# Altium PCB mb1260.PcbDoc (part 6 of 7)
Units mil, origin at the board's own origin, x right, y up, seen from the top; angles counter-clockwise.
Board outline 3189.01 x 3818.89 mil, 6 copper layers (TOP, L2_GND, L3_VCC, L4_SIG, L5_GND, BOTTOM), stack 62.2 mil thick; 308 components, 287 nets, 1220 pads, 851 vias.
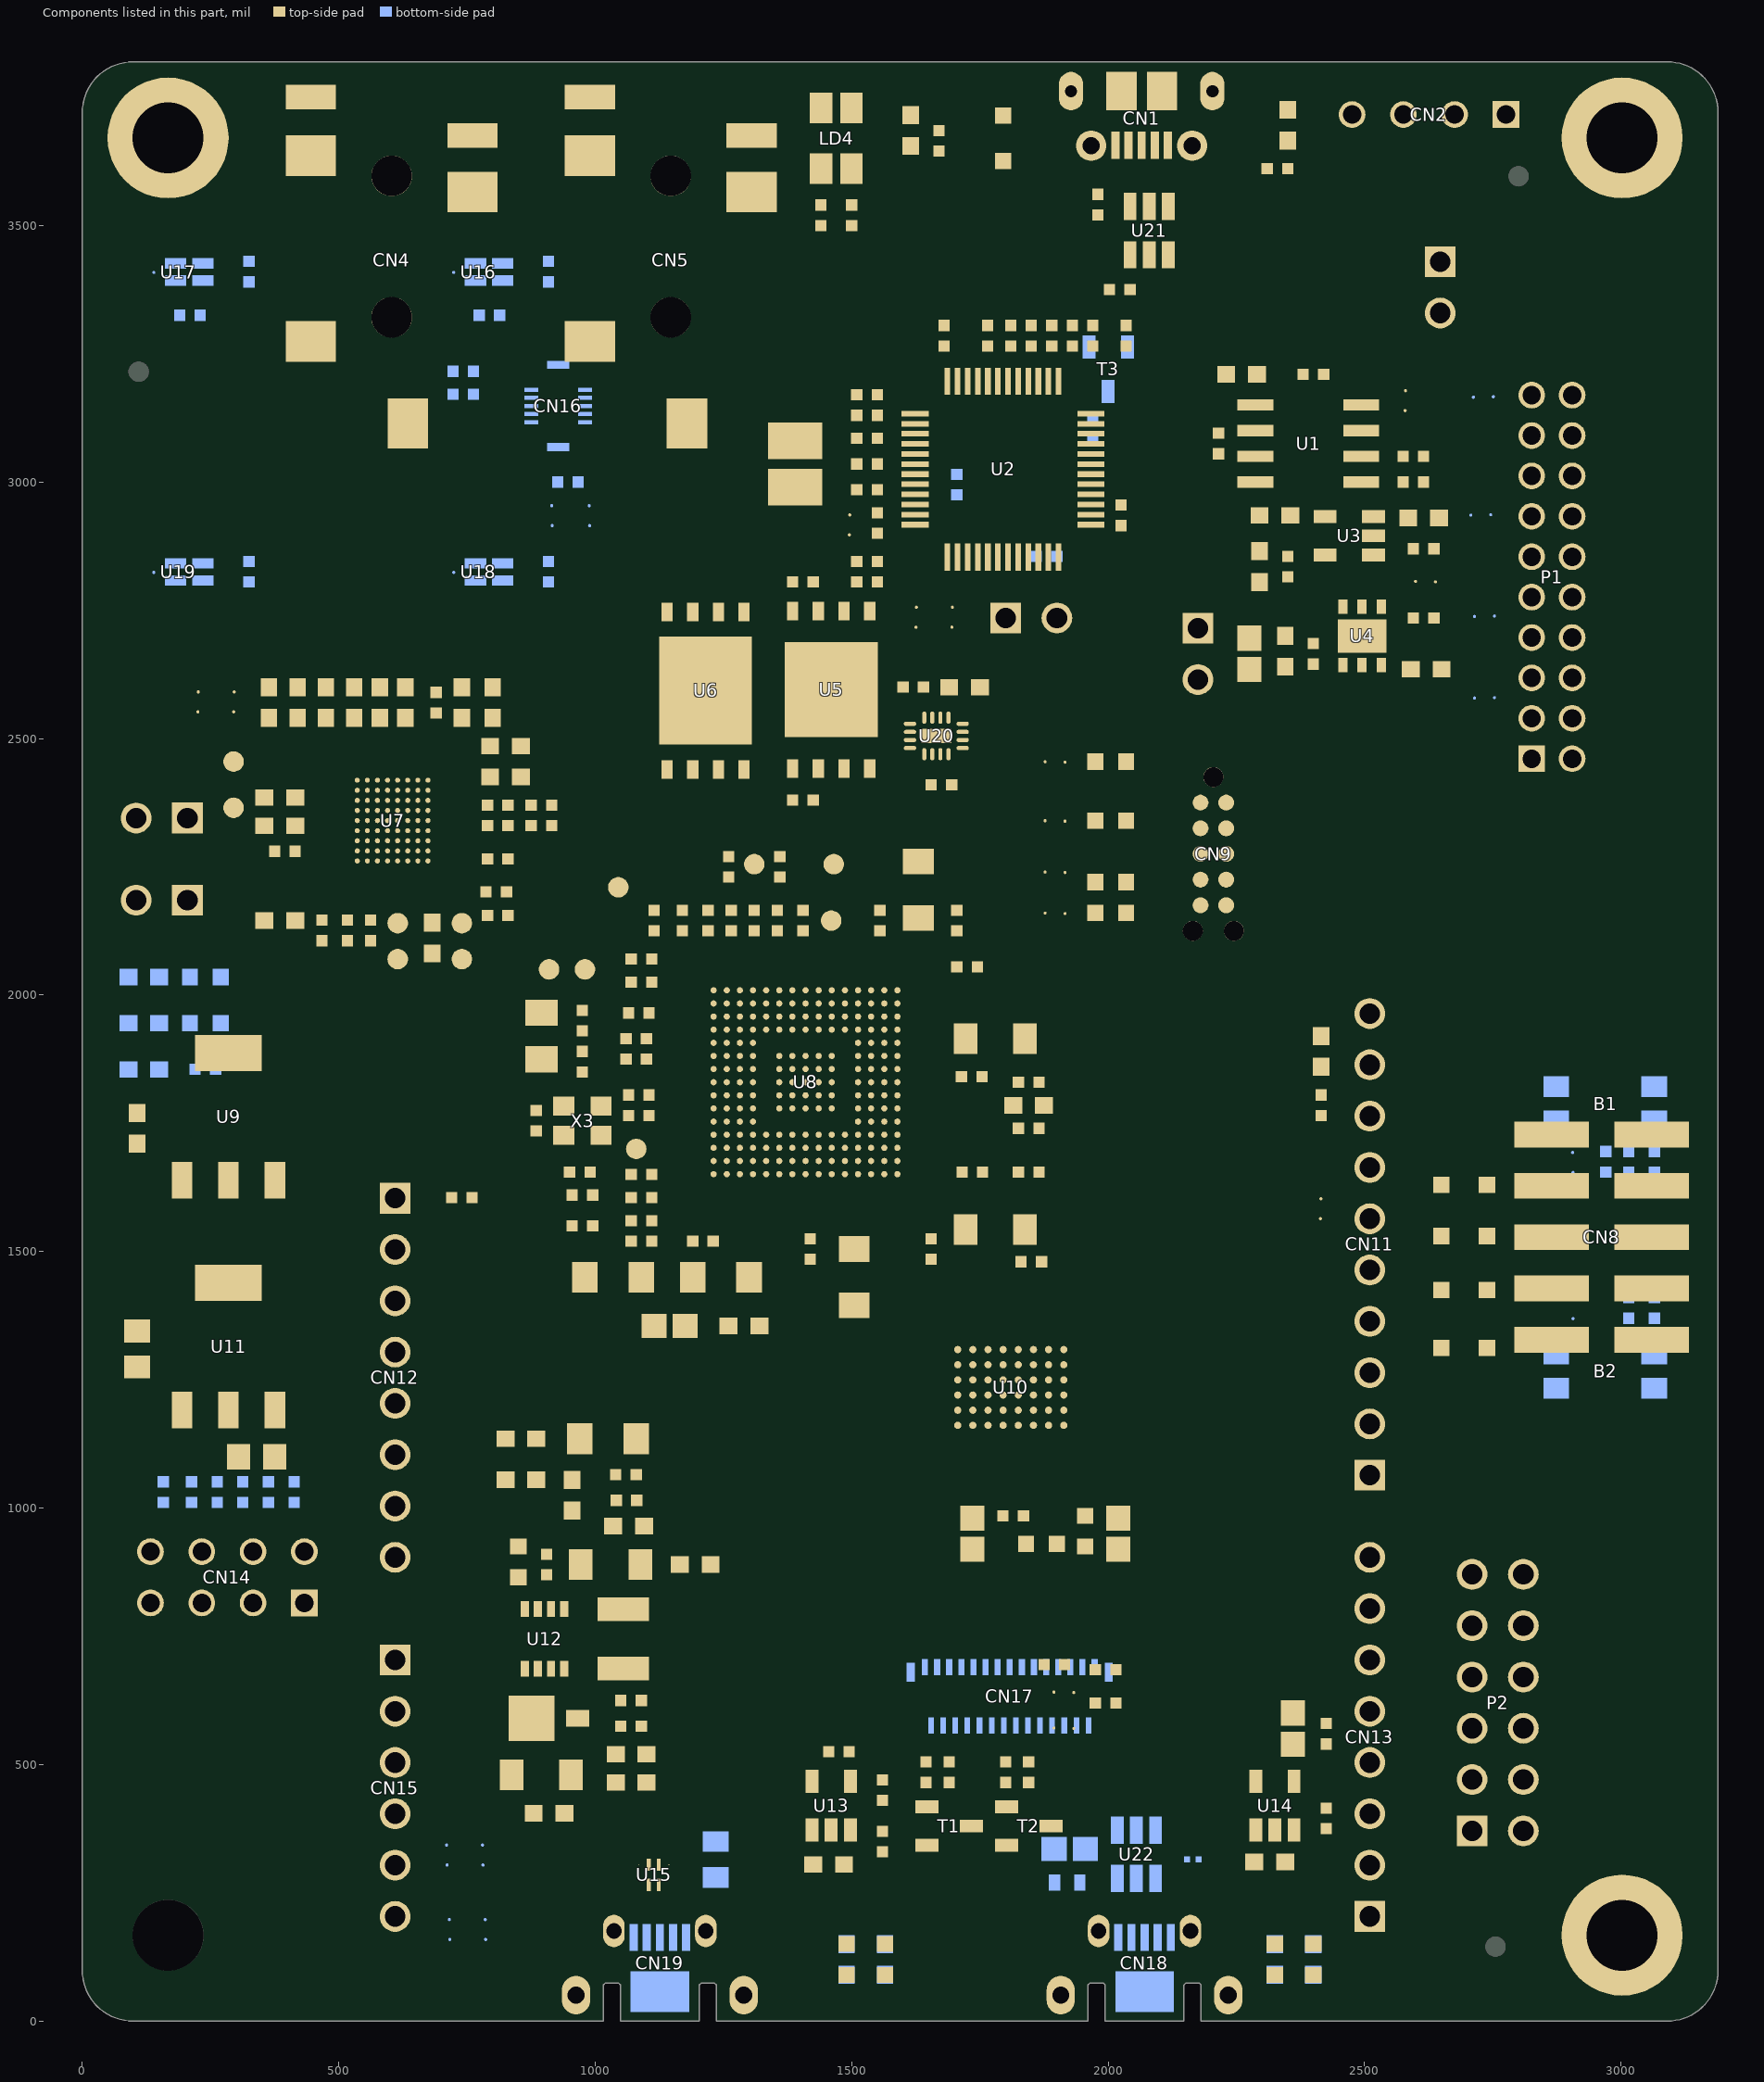
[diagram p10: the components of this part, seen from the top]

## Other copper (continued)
L2_GND (plane layer: these items are gaps in the copper):
  rectangle: -21.66,-14.67 557.59,549.61
  rectangle: 2273.23,973.39 2419.77,1532.61
  pour cut-out: -6000,-8000 -5990,-8000 -5990,-7990 -6000,-7990
  pour cut-out: -6000,-8000 -5990,-8000 -5990,-7990 -6000,-7990
  pour cut-out: -6000,-8000 -5990,-8000 -5990,-7990 -6000,-7990
  pour cut-out: -6000,-8000 -5990,-8000 -5990,-7990 -6000,-7990
  pour cut-out: -6000,-8000 -5990,-8000 -5990,-7990 -6000,-7990
  pour cut-out: -6000,-8000 -5990,-8000 -5990,-7990 -6000,-7990
  pour cut-out: -6000,-8000 -5990,-8000 -5990,-7990 -6000,-7990
  pour cut-out: -6000,-8000 -5990,-8000 -5990,-7990 -6000,-7990
  pour cut-out: -6000,-8000 -5990,-8000 -5990,-7990 -6000,-7990
  pour cut-out: -6000,-8000 -5990,-8000 -5990,-7990 -6000,-7990
  pour cut-out: -6000,-8000 -5990,-8000 -5990,-7990 -6000,-7990
  pour cut-out: -6000,-8000 -5990,-8000 -5990,-7990 -6000,-7990
  pour cut-out: -6000,-8000 -5990,-8000 -5990,-7990 -6000,-7990
  pour cut-out: -6000,-8000 -5990,-8000 -5990,-7990 -6000,-7990
  pour cut-out: -6000,-8000 -5990,-8000 -5990,-7990 -6000,-7990
  pour cut-out: -6000,-8000 -5990,-8000 -5990,-7990 -6000,-7990
  pour cut-out: -6000,-8000 -5990,-8000 -5990,-7990 -6000,-7990
  pour cut-out: -6000,-8000 -5990,-8000 -5990,-7990 -6000,-7990
  pour cut-out: -6000,-8000 -5990,-8000 -5990,-7990 -6000,-7990
  pour cut-out: -6000,-8000 -5990,-8000 -5990,-7990 -6000,-7990
  pour cut-out: -6000,-8000 -5990,-8000 -5990,-7990 -6000,-7990
  pour cut-out: -6000,-8000 -5990,-8000 -5990,-7990 -6000,-7990
  pour cut-out: -6000,-8000 -5990,-8000 -5990,-7990 -6000,-7990
  pour cut-out: -6000,-8000 -5990,-8000 -5990,-7990 -6000,-7990
  pour cut-out: -6000,-8000 -5990,-8000 -5990,-7990 -6000,-7990
  pour cut-out: -6000,-8000 -5990,-8000 -5990,-7990 -6000,-7990
  pour cut-out: -6000,-8000 -5990,-8000 -5990,-7990 -6000,-7990
  pour cut-out: -6000,-8000 -5990,-8000 -5990,-7990 -6000,-7990
  pour cut-out: -6000,-8000 -5990,-8000 -5990,-7990 -6000,-7990
  pour cut-out: -6000,-8000 -5990,-8000 -5990,-7990 -6000,-7990
  pour cut-out: -6000,-8000 -5990,-8000 -5990,-7990 -6000,-7990
  pour cut-out: -6000,-8000 -5990,-8000 -5990,-7990 -6000,-7990
  pour cut-out: -6000,-8000 -5990,-8000 -5990,-7990 -6000,-7990
  pour cut-out: -6000,-8000 -5990,-8000 -5990,-7990 -6000,-7990
  pour cut-out: -6000,-8000 -5990,-8000 -5990,-7990 -6000,-7990
  pour cut-out: -6000,-8000 -5990,-8000 -5990,-7990 -6000,-7990
  pour cut-out: -6000,-8000 -5990,-8000 -5990,-7990 -6000,-7990
  pour cut-out: -6000,-8000 -5990,-8000 -5990,-7990 -6000,-7990
  pour cut-out: -6000,-8000 -5990,-8000 -5990,-7990 -6000,-7990
  pour cut-out: -6000,-8000 -5990,-8000 -5990,-7990 -6000,-7990
  pour cut-out: -6000,-8000 -5990,-8000 -5990,-7990 -6000,-7990
  pour cut-out: -6000,-8000 -5990,-8000 -5990,-7990 -6000,-7990
  pour cut-out: -6000,-8000 -5990,-8000 -5990,-7990 -6000,-7990
  pour cut-out: -6000,-8000 -5990,-8000 -5990,-7990 -6000,-7990
  pour cut-out: -6000,-8000 -5990,-8000 -5990,-7990 -6000,-7990
  pour cut-out: -6000,-8000 -5990,-8000 -5990,-7990 -6000,-7990
  pour cut-out: -6000,-8000 -5990,-8000 -5990,-7990 -6000,-7990
  pour cut-out: -6000,-8000 -5990,-8000 -5990,-7990 -6000,-7990
  pour cut-out: -6000,-8000 -5990,-8000 -5990,-7990 -6000,-7990
  pour cut-out: -6000,-8000 -5990,-8000 -5990,-7990 -6000,-7990
  pour cut-out: -6000,-8000 -5990,-8000 -5990,-7990 -6000,-7990
  pour cut-out: -6000,-8000 -5990,-8000 -5990,-7990 -6000,-7990
  pour cut-out: -6000,-8000 -5990,-8000 -5990,-7990 -6000,-7990
  pour cut-out: -6000,-8000 -5990,-8000 -5990,-7990 -6000,-7990
  pour cut-out: -6000,-8000 -5990,-8000 -5990,-7990 -6000,-7990
  pour cut-out: -6000,-8000 -5990,-8000 -5990,-7990 -6000,-7990
  pour cut-out: -6000,-8000 -5990,-8000 -5990,-7990 -6000,-7990
  pour cut-out: -6000,-8000 -5990,-8000 -5990,-7990 -6000,-7990
  pour cut-out: -6000,-8000 -5990,-8000 -5990,-7990 -6000,-7990
  pour cut-out: -6000,-8000 -5990,-8000 -5990,-7990 -6000,-7990
  pour cut-out: -6000,-8000 -5990,-8000 -5990,-7990 -6000,-7990
  pour cut-out: -6000,-8000 -5990,-8000 -5990,-7990 -6000,-7990
  pour cut-out: -6000,-8000 -5990,-8000 -5990,-7990 -6000,-7990
  pour cut-out: -6000,-8000 -5990,-8000 -5990,-7990 -6000,-7990
  pour cut-out: -6000,-8000 -5990,-8000 -5990,-7990 -6000,-7990
  pour cut-out: -6000,-8000 -5990,-8000 -5990,-7990 -6000,-7990
  pour cut-out: -6000,-8000 -5990,-8000 -5990,-7990 -6000,-7990
  pour cut-out: -6000,-8000 -5990,-8000 -5990,-7990 -6000,-7990
  pour cut-out: -6000,-8000 -5990,-8000 -5990,-7990 -6000,-7990
  pour cut-out: -6000,-8000 -5990,-8000 -5990,-7990 -6000,-7990
  pour cut-out: 2240.77,2425 2239.55,2434.26 2235.98,2442.88 2230.29,2450.29 2222.88,2455.98 2214.26,2459.55 2205,2460.77 2195.74,2459.55 2187.12,2455.98 2179.71,2450.29 2174.02,2442.88 2170.45,2434.26 2169.23,2425 2170.45,2415.74 2174.02,2407.12 2179.71,2399.71 2187.12,2394.02 2195.74,2390.45 2205,2389.23 2214.26,2390.45 2222.88,2394.02 2230.29,2399.71 2235.98,2407.12 2239.55,2415.74 2240.77,2425
  pour cut-out: 2280.73,2125 2279.51,2134.26 2275.94,2142.88 2270.25,2150.29 2262.84,2155.97 2254.22,2159.55 2244.96,2160.77 2235.7,2159.55 2227.08,2155.97 2219.67,2150.29 2213.99,2142.88 2210.41,2134.26 2209.19,2125 2210.41,2115.74 2213.99,2107.12 2219.67,2099.71 2227.08,2094.03 2235.7,2090.45 2244.96,2089.23 2254.22,2090.45 2262.84,2094.03 2270.25,2099.71 2275.94,2107.12 2279.51,2115.74 2280.73,2125
  pour cut-out: 2200.81,2125 2199.59,2134.26 2196.01,2142.88 2190.33,2150.29 2182.92,2155.98 2174.3,2159.55 2165.04,2160.77 2155.78,2159.55 2147.16,2155.98 2139.75,2150.29 2134.06,2142.88 2130.49,2134.26 2129.27,2125 2130.49,2115.74 2134.06,2107.12 2139.75,2099.71 2147.16,2094.02 2155.78,2090.45 2165.04,2089.23 2174.3,2090.45 2182.92,2094.02 2190.33,2099.71 2196.01,2107.12 2199.59,2115.74 2200.81,2125
  pour cut-out: 1201.99,3596.61 1200.12,3610.8 1194.64,3624.02 1185.93,3635.38 1174.57,3644.09 1161.35,3649.57 1147.16,3651.44 1132.97,3649.57 1119.75,3644.09 1108.39,3635.38 1099.68,3624.02 1094.2,3610.8 1092.33,3596.61 1094.2,3582.42 1099.68,3569.2 1108.39,3557.84 1119.75,3549.13 1132.97,3543.65 1147.16,3541.78 1161.35,3543.65 1174.57,3549.13 1185.93,3557.84 1194.64,3569.2 1200.12,3582.42 1201.99,3596.61
  pour cut-out: 657.98,3596.61 656.11,3610.8 650.64,3624.03 641.92,3635.38 630.57,3644.1 617.34,3649.57 603.15,3651.44 588.96,3649.57 575.73,3644.1 564.38,3635.38 555.66,3624.03 550.19,3610.8 548.32,3596.61 550.19,3582.42 555.66,3569.19 564.38,3557.84 575.73,3549.12 588.96,3543.65 603.15,3541.78 617.34,3543.65 630.57,3549.12 641.92,3557.84 650.64,3569.19 656.11,3582.42 657.98,3596.61
  pour cut-out: 657.98,3321.02 656.11,3335.21 650.64,3348.43 641.92,3359.79 630.57,3368.5 617.34,3373.98 603.15,3375.85 588.96,3373.98 575.73,3368.5 564.38,3359.79 555.66,3348.43 550.19,3335.21 548.32,3321.02 550.19,3306.83 555.66,3293.6 564.38,3282.25 575.73,3273.53 588.96,3268.06 603.15,3266.19 617.34,3268.06 630.57,3273.53 641.92,3282.25 650.64,3293.6 656.11,3306.83 657.98,3321.02
  pour cut-out: -6000,-8000 -5990,-8000 -5990,-7990 -6000,-7990
  pour cut-out: -6000,-8000 -5990,-8000 -5990,-7990 -6000,-7990
  pour cut-out: -6000,-8000 -5990,-8000 -5990,-7990 -6000,-7990
  pour cut-out: -6000,-8000 -5990,-8000 -5990,-7990 -6000,-7990
  pour cut-out: -6000,-8000 -5990,-8000 -5990,-7990 -6000,-7990
  pour cut-out: -6000,-8000 -5990,-8000 -5990,-7990 -6000,-7990
  pour cut-out: -6000,-8000 -5990,-8000 -5990,-7990 -6000,-7990
  pour cut-out: -6000,-8000 -5990,-8000 -5990,-7990 -6000,-7990
  pour cut-out: -6000,-8000 -5990,-8000 -5990,-7990 -6000,-7990
  pour cut-out: -6000,-8000 -5990,-8000 -5990,-7990 -6000,-7990
  pour cut-out: -6000,-8000 -5990,-8000 -5990,-7990 -6000,-7990
  pour cut-out: -6000,-8000 -5990,-8000 -5990,-7990 -6000,-7990
  pour cut-out: -6000,-8000 -5990,-8000 -5990,-7990 -6000,-7990
  pour cut-out: -6000,-8000 -5990,-8000 -5990,-7990 -6000,-7990
  pour cut-out: 1201.99,3321.02 1200.12,3335.21 1194.64,3348.43 1185.93,3359.79 1174.57,3368.5 1161.35,3373.98 1147.16,3375.85 1132.97,3373.98 1119.75,3368.5 1108.39,3359.79 1099.68,3348.43 1094.2,3335.21 1092.33,3321.02 1094.2,3306.83 1099.68,3293.6 1108.39,3282.25 1119.75,3273.54 1132.97,3268.06 1147.16,3266.19 1161.35,3268.06 1174.57,3273.54 1185.93,3282.25 1194.64,3293.6 1200.12,3306.83 1201.99,3321.02
  pour cut-out: -6000,-8000 -5990,-8000 -5990,-7990 -6000,-7990
  pour cut-out: -6000,-8000 -5990,-8000 -5990,-7990 -6000,-7990
  pour cut-out: -6000,-8000 -5990,-8000 -5990,-7990 -6000,-7990
  pour cut-out: -6000,-8000 -5990,-8000 -5990,-7990 -6000,-7990
  pour cut-out: -6000,-8000 -5990,-8000 -5990,-7990 -6000,-7990
  pour cut-out: -6000,-8000 -5990,-8000 -5990,-7990 -6000,-7990
  pour cut-out: -6000,-8000 -5990,-8000 -5990,-7990 -6000,-7990
  pour cut-out: -6000,-8000 -5990,-8000 -5990,-7990 -6000,-7990
  pour cut-out: -6000,-8000 -5990,-8000 -5990,-7990 -6000,-7990
  pour cut-out: -6000,-8000 -5990,-8000 -5990,-7990 -6000,-7990
  pour cut-out: -6000,-8000 -5990,-8000 -5990,-7990 -6000,-7990
  pour cut-out: -6000,-8000 -5990,-8000 -5990,-7990 -6000,-7990
  pour cut-out: -6000,-8000 -5990,-8000 -5990,-7990 -6000,-7990
  pour cut-out: -6000,-8000 -5990,-8000 -5990,-7990 -6000,-7990
  pour cut-out: -6000,-8000 -5990,-8000 -5990,-7990 -6000,-7990
  pour cut-out: -6000,-8000 -5990,-8000 -5990,-7990 -6000,-7990
  pour cut-out: -6000,-8000 -5990,-8000 -5990,-7990 -6000,-7990
  pour cut-out: -6000,-8000 -5990,-8000 -5990,-7990 -6000,-7990
  pour cut-out: -6000,-8000 -5990,-8000 -5990,-7990 -6000,-7990
  pour cut-out: -6000,-8000 -5990,-8000 -5990,-7990 -6000,-7990
  pour cut-out: -6000,-8000 -5990,-8000 -5990,-7990 -6000,-7990
  pour cut-out: -6000,-8000 -5990,-8000 -5990,-7990 -6000,-7990
  pour cut-out: -6000,-8000 -5990,-8000 -5990,-7990 -6000,-7990
  pour cut-out: -6000,-8000 -5990,-8000 -5990,-7990 -6000,-7990
  pour cut-out: -6000,-8000 -5990,-8000 -5990,-7990 -6000,-7990
  pour cut-out: -6000,-8000 -5990,-8000 -5990,-7990 -6000,-7990
  pour cut-out: -6000,-8000 -5990,-8000 -5990,-7990 -6000,-7990
  pour cut-out: -6000,-8000 -5990,-8000 -5990,-7990 -6000,-7990
  pour cut-out: -6000,-8000 -5990,-8000 -5990,-7990 -6000,-7990
  pour cut-out: -6000,-8000 -5990,-8000 -5990,-7990 -6000,-7990
  pour cut-out: -6000,-8000 -5990,-8000 -5990,-7990 -6000,-7990
  pour cut-out: -6000,-8000 -5990,-8000 -5990,-7990 -6000,-7990
  pour cut-out: -6000,-8000 -5990,-8000 -5990,-7990 -6000,-7990
  pour cut-out: -6000,-8000 -5990,-8000 -5990,-7990 -6000,-7990
  pour cut-out: -6000,-8000 -5990,-8000 -5990,-7990 -6000,-7990
  pour cut-out: -6000,-8000 -5990,-8000 -5990,-7990 -6000,-7990
  pour cut-out: -6000,-8000 -5990,-8000 -5990,-7990 -6000,-7990
  pour cut-out: -6000,-8000 -5990,-8000 -5990,-7990 -6000,-7990
  pour cut-out: -6000,-8000 -5990,-8000 -5990,-7990 -6000,-7990
  pour cut-out: -6000,-8000 -5990,-8000 -5990,-7990 -6000,-7990
  pour cut-out: -6000,-8000 -5990,-8000 -5990,-7990 -6000,-7990
  pour cut-out: -6000,-8000 -5990,-8000 -5990,-7990 -6000,-7990
  region: 833,1806 808,1831 808,2007 831,2030 947,2030 962,2015 990,2015 1020,1985 1020,1965 1030,1955 1116,1955 1116.5,1954.5 1121.5,1954.5 1133,1943 1163,1943 1164,1942 1164,1938 1163,1937 1130,1937 1122,1945 1020,1945 1004,1961 1004,1984 989,1999 953,1999 937,2015 840,2015 825,2000 825,1840 840,1825 1020,1825 1030,1835 1116,1835 1143,1862 1159,1862 1160,1861 1160,1855 1158,1853 1147,1853 1111,1817 1039,1817 1028,1806
  lines w10: 784.59,429.14 784.59,925.86 ; 784.59,429.14 784.59,429.14 ; 784.59,429.14 785.71,426.44 786.17,425.32 ; 784.59,925.86 786.17,929.68 859.59,1003.1 859.59,1155.86 ; 784.59,925.86 784.59,925.86 ; 786.17,425.32 786.17,425.32 ; 786.17,425.32 855.32,356.17 859.14,354.59 ; 859.14,354.59 859.14,354.59 ; 859.14,354.59 1030.86,354.59 1034.68,356.17 1063.83,385.32 1065.41,389.14 ; 859.59,1155.86 861.17,1159.68 875.32,1173.83 879.14,1175.41 1115.86,1175.41 ; 859.59,1155.86 859.59,1155.86 ; 1065.41,389.14 1065.41,389.14 ; 1065.41,389.14 1065.41,586.9 1083.1,604.59 1165.86,604.59 ; 1115.86,1175.41 1119.68,1173.83 1188.83,1104.68 ; 1115.86,1175.41 1115.86,1175.41 ; 1165.86,604.59 1165.86,604.59 ; 1165.86,604.59 1168.56,605.71 1169.68,606.17 ; 1169.68,606.17 1169.69,606.17 ; 1169.69,606.17 1188.83,625.32 1190.41,629.14 ; 1188.83,1104.68 1189.29,1103.56 1190.41,1100.86 ; 1188.83,1104.68 1188.83,1104.68 ; 1190.41,629.14 1190.41,629.14 ; 1190.41,629.14 1190.41,1100.86 ; 1190.41,1100.86 1190.41,1100.86 ; 14.63,555.02 14.63,3720.07 14.68,3720.19 14.63,3720.31 14.93,3727.17 15.04,3727.4 14.97,3727.64 15.87,3734.46 16,3734.67 15.95,3734.92 17.44,3741.63 17.58,3741.84 17.56,3742.09 19.63,3748.64 19.79,3748.84 19.79,3749.09 22.42,3755.44 22.6,3755.61 22.62,3755.86 25.79,3761.96 25.99,3762.12 26.03,3762.37 29.72,3768.17 29.93,3768.31 29.99,3768.55 34.18,3774 34.39,3774.13 34.48,3774.37 39.12,3779.43 39.35,3779.54 39.46,3779.77 44.52,3784.41 44.76,3784.5 44.89,3784.71 50.34,3788.9 50.58,3788.96 50.73,3789.17 56.52,3792.86 56.77,3792.9 56.93,3793.1 63.03,3796.27 63.28,3796.29 63.45,3796.47 69.8,3799.1 70.06,3799.1 70.25,3799.26 76.8,3801.33 77.05,3801.31 77.26,3801.45 83.97,3802.94 84.22,3802.89 84.43,3803.02 91.25,3803.92 91.49,3803.85 91.72,3803.96 98.58,3804.26 98.7,3804.21 98.82,3804.26 3090.19,3804.26 3090.31,3804.21 3090.43,3804.26 3097.29,3803.96 3097.52,3803.85 3097.76,3803.92 3104.58,3803.02 3104.79,3802.89 3105.04,3802.94 3111.75,3801.45 3111.96,3801.31 3112.21,3801.33 3118.76,3799.26 3118.95,3799.1 3119.2,3799.1 3125.55,3796.47 3125.73,3796.29 3125.98,3796.27 3132.08,3793.1 3132.24,3792.9 3132.49,3792.86 3138.28,3789.17 3138.43,3788.96 3138.67,3788.9 3144.12,3784.71 3144.25,3784.5 3144.48,3784.41 3149.55,3779.77 3149.66,3779.54 3149.89,3779.43 3154.53,3774.37 3154.61,3774.13 3154.83,3774 3159.02,3768.55 3159.08,3768.31 3159.29,3768.16 3162.98,3762.37 3163.02,3762.12 3163.22,3761.96 3166.39,3755.86 3166.41,3755.61 3166.59,3755.43 3169.22,3749.09 3169.22,3748.83 3169.38,3748.64 3171.45,3742.09 3171.42,3741.84 3171.57,3741.63 3173.06,3734.92 3173.01,3734.67 3173.14,3734.46 3174.03,3727.64 3173.97,3727.4 3174.08,3727.17 3174.38,3720.31 3174.33,3720.19 3174.38,3720.07 3174.38,98.82 3174.33,98.7 3174.38,98.58 3174.08,91.72 3173.97,91.49 3174.03,91.25 3173.14,84.43 3173.01,84.22 3173.06,83.97 3171.57,77.26 3171.42,77.05 3171.45,76.8 3169.38,70.25 3169.22,70.05 3169.22,69.8 3166.59,63.45 3166.41,63.28 3166.39,63.03 3163.22,56.93 3163.02,56.77 3162.98,56.52 3159.29,50.72 3159.08,50.58 3159.02,50.34 3154.83,44.89 3154.61,44.76 3154.53,44.52 3149.89,39.46 3149.66,39.35 3149.55,39.12 3144.48,34.48 3144.25,34.39 3144.12,34.18 3138.67,29.99 3138.43,29.93 3138.28,29.72 3132.49,26.03 3132.24,25.99 3132.08,25.79 3125.98,22.62 3125.73,22.6 3125.55,22.42 3119.2,19.79 3118.95,19.79 3118.76,19.63 3112.21,17.56 3111.96,17.58 3111.75,17.44 3105.04,15.95 3104.79,16 3104.58,15.87 3097.76,14.97 3097.52,15.04 3097.29,14.93 3090.43,14.63 3090.31,14.68 3090.19,14.63 2201.15,14.63 2197.32,16.21 2195.74,20.04 2195.74,76.34 2183.23,88.85 2145.52,88.85 2133.01,76.34 2133.01,20.04 2131.42,16.21 2127.6,14.63 2014.14,14.63 2010.32,16.21 2008.73,20.04 2008.73,76.34 1996.22,88.85 1958.51,88.85 1946,76.34 1946,20.04 1944.42,16.21 1940.59,14.63 1256.26,14.63 1252.43,16.21 1250.85,20.04 1250.85,76.34 1238.34,88.85 1200.63,88.85 1188.12,76.34 1188.12,20.04 1186.54,16.21 1182.71,14.63 1069.25,14.63 1065.43,16.21 1063.84,20.04 1063.84,76.34 1051.33,88.85 1013.62,88.85 1001.11,76.34 1001.11,20.04 999.53,16.21 995.7,14.63 563,14.63 559.17,16.21 557.59,20.04 557.59,549.61 20.04,549.61 16.21,551.19 14.63,555.02
  lines w20: 780,425 780,930 855,1005 855,1160 875,1180 1120,1180 1195,1105 1195,625 1170,600 1085,600 1070,585 1070,385 1035,350 855,350 780,425
L3_VCC (plane layer: these items are gaps in the copper):
  drawing of 1374 lines, arcs and shapes, not listed
L5_GND (plane layer: these items are gaps in the copper):
  rectangle: 2273.23,973.39 2419.77,1532.61
  rectangle: -22.66,-22.67 552.49,544.51
  pour cut-out: -6000,-8000 -5990,-8000 -5990,-7990 -6000,-7990
  pour cut-out: -6000,-8000 -5990,-8000 -5990,-7990 -6000,-7990
  pour cut-out: -6000,-8000 -5990,-8000 -5990,-7990 -6000,-7990
  pour cut-out: -6000,-8000 -5990,-8000 -5990,-7990 -6000,-7990
  pour cut-out: -6000,-8000 -5990,-8000 -5990,-7990 -6000,-7990
  pour cut-out: -6000,-8000 -5990,-8000 -5990,-7990 -6000,-7990
  pour cut-out: -6000,-8000 -5990,-8000 -5990,-7990 -6000,-7990
  pour cut-out: -6000,-8000 -5990,-8000 -5990,-7990 -6000,-7990
  pour cut-out: -6000,-8000 -5990,-8000 -5990,-7990 -6000,-7990
  pour cut-out: -6000,-8000 -5990,-8000 -5990,-7990 -6000,-7990
  pour cut-out: -6000,-8000 -5990,-8000 -5990,-7990 -6000,-7990
  pour cut-out: -6000,-8000 -5990,-8000 -5990,-7990 -6000,-7990
  pour cut-out: -6000,-8000 -5990,-8000 -5990,-7990 -6000,-7990
  pour cut-out: -6000,-8000 -5990,-8000 -5990,-7990 -6000,-7990
  pour cut-out: 2240.77,2425 2239.55,2434.26 2235.98,2442.88 2230.29,2450.29 2222.88,2455.98 2214.26,2459.55 2205,2460.77 2195.74,2459.55 2187.12,2455.98 2179.71,2450.29 2174.02,2442.88 2170.45,2434.26 2169.23,2425 2170.45,2415.74 2174.02,2407.12 2179.71,2399.71 2187.12,2394.02 2195.74,2390.45 2205,2389.23 2214.26,2390.45 2222.88,2394.02 2230.29,2399.71 2235.98,2407.12 2239.55,2415.74 2240.77,2425
  pour cut-out: 2280.73,2125 2279.51,2134.26 2275.94,2142.88 2270.25,2150.29 2262.84,2155.97 2254.22,2159.55 2244.96,2160.77 2235.7,2159.55 2227.08,2155.97 2219.67,2150.29 2213.99,2142.88 2210.41,2134.26 2209.19,2125 2210.41,2115.74 2213.99,2107.12 2219.67,2099.71 2227.08,2094.03 2235.7,2090.45 2244.96,2089.23 2254.22,2090.45 2262.84,2094.03 2270.25,2099.71 2275.94,2107.12 2279.51,2115.74 2280.73,2125
  pour cut-out: 2200.81,2125 2199.59,2134.26 2196.01,2142.88 2190.33,2150.29 2182.92,2155.98 2174.3,2159.55 2165.04,2160.77 2155.78,2159.55 2147.16,2155.98 2139.75,2150.29 2134.06,2142.88 2130.49,2134.26 2129.27,2125 2130.49,2115.74 2134.06,2107.12 2139.75,2099.71 2147.16,2094.02 2155.78,2090.45 2165.04,2089.23 2174.3,2090.45 2182.92,2094.02 2190.33,2099.71 2196.01,2107.12 2199.59,2115.74 2200.81,2125
  pour cut-out: 1201.99,3596.61 1200.12,3610.8 1194.64,3624.02 1185.93,3635.38 1174.57,3644.09 1161.35,3649.57 1147.16,3651.44 1132.97,3649.57 1119.75,3644.09 1108.39,3635.38 1099.68,3624.02 1094.2,3610.8 1092.33,3596.61 1094.2,3582.42 1099.68,3569.2 1108.39,3557.84 1119.75,3549.13 1132.97,3543.65 1147.16,3541.78 1161.35,3543.65 1174.57,3549.13 1185.93,3557.84 1194.64,3569.2 1200.12,3582.42 1201.99,3596.61
  pour cut-out: 657.98,3596.61 656.11,3610.8 650.64,3624.03 641.92,3635.38 630.57,3644.1 617.34,3649.57 603.15,3651.44 588.96,3649.57 575.73,3644.1 564.38,3635.38 555.66,3624.03 550.19,3610.8 548.32,3596.61 550.19,3582.42 555.66,3569.19 564.38,3557.84 575.73,3549.12 588.96,3543.65 603.15,3541.78 617.34,3543.65 630.57,3549.12 641.92,3557.84 650.64,3569.19 656.11,3582.42 657.98,3596.61
  pour cut-out: 657.98,3321.02 656.11,3335.21 650.64,3348.43 641.92,3359.79 630.57,3368.5 617.34,3373.98 603.15,3375.85 588.96,3373.98 575.73,3368.5 564.38,3359.79 555.66,3348.43 550.19,3335.21 548.32,3321.02 550.19,3306.83 555.66,3293.6 564.38,3282.25 575.73,3273.53 588.96,3268.06 603.15,3266.19 617.34,3268.06 630.57,3273.53 641.92,3282.25 650.64,3293.6 656.11,3306.83 657.98,3321.02
  pour cut-out: 1201.99,3321.02 1200.12,3335.21 1194.64,3348.43 1185.93,3359.79 1174.57,3368.5 1161.35,3373.98 1147.16,3375.85 1132.97,3373.98 1119.75,3368.5 1108.39,3359.79 1099.68,3348.43 1094.2,3335.21 1092.33,3321.02 1094.2,3306.83 1099.68,3293.6 1108.39,3282.25 1119.75,3273.54 1132.97,3268.06 1147.16,3266.19 1161.35,3268.06 1174.57,3273.54 1185.93,3282.25 1194.64,3293.6 1200.12,3306.83 1201.99,3321.02
  lines w10: 14.63,555.02 14.63,3720.07 14.68,3720.19 14.63,3720.31 14.93,3727.17 15.04,3727.4 14.97,3727.64 15.87,3734.46 16,3734.67 15.95,3734.92 17.44,3741.63 17.58,3741.84 17.56,3742.09 19.63,3748.64 19.79,3748.84 19.79,3749.09 22.42,3755.44 22.6,3755.61 22.62,3755.86 25.79,3761.96 25.99,3762.12 26.03,3762.37 29.72,3768.17 29.93,3768.31 29.99,3768.55 34.18,3774 34.39,3774.13 34.48,3774.37 39.12,3779.43 39.35,3779.54 39.46,3779.77 44.52,3784.41 44.76,3784.5 44.89,3784.71 50.34,3788.9 50.58,3788.96 50.73,3789.17 56.52,3792.86 56.77,3792.9 56.93,3793.1 63.03,3796.27 63.28,3796.29 63.45,3796.47 69.8,3799.1 70.06,3799.1 70.25,3799.26 76.8,3801.33 77.05,3801.31 77.26,3801.45 83.97,3802.94 84.22,3802.89 84.43,3803.02 91.25,3803.92 91.49,3803.85 91.72,3803.96 98.58,3804.26 98.7,3804.21 98.82,3804.26 3090.19,3804.26 3090.31,3804.21 3090.43,3804.26 3097.29,3803.96 3097.52,3803.85 3097.76,3803.92 3104.58,3803.02 3104.79,3802.89 3105.04,3802.94 3111.75,3801.45 3111.96,3801.31 3112.21,3801.33 3118.76,3799.26 3118.95,3799.1 3119.2,3799.1 3125.55,3796.47 3125.73,3796.29 3125.98,3796.27 3132.08,3793.1 3132.24,3792.9 3132.49,3792.86 3138.28,3789.17 3138.43,3788.96 3138.67,3788.9 3144.12,3784.71 3144.25,3784.5 3144.48,3784.41 3149.55,3779.77 3149.66,3779.54 3149.89,3779.43 3154.53,3774.37 3154.61,3774.13 3154.83,3774 3159.02,3768.55 3159.08,3768.31 3159.29,3768.16 3162.98,3762.37 3163.02,3762.12 3163.22,3761.96 3166.39,3755.86 3166.41,3755.61 3166.59,3755.43 3169.22,3749.09 3169.22,3748.83 3169.38,3748.64 3171.45,3742.09 3171.42,3741.84 3171.57,3741.63 3173.06,3734.92 3173.01,3734.67 3173.14,3734.46 3174.03,3727.64 3173.97,3727.4 3174.08,3727.17 3174.38,3720.31 3174.33,3720.19 3174.38,3720.07 3174.38,98.82 3174.33,98.7 3174.38,98.58 3174.08,91.72 3173.97,91.49 3174.03,91.25 3173.14,84.43 3173.01,84.22 3173.06,83.97 3171.57,77.26 3171.42,77.05 3171.45,76.8 3169.38,70.25 3169.22,70.05 3169.22,69.8 3166.59,63.45 3166.41,63.28 3166.39,63.03 3163.22,56.93 3163.02,56.77 3162.98,56.52 3159.29,50.72 3159.08,50.58 3159.02,50.34 3154.83,44.89 3154.61,44.76 3154.53,44.52 3149.89,39.46 3149.66,39.35 3149.55,39.12 3144.48,34.48 3144.25,34.39 3144.12,34.18 3138.67,29.99 3138.43,29.93 3138.28,29.72 3132.49,26.03 3132.24,25.99 3132.08,25.79 3125.98,22.62 3125.73,22.6 3125.55,22.42 3119.2,19.79 3118.95,19.79 3118.76,19.63 3112.21,17.56 3111.96,17.58 3111.75,17.44 3105.04,15.95 3104.79,16 3104.58,15.87 3097.76,14.97 3097.52,15.04 3097.29,14.93 3090.43,14.63 3090.31,14.68 3090.19,14.63 2201.15,14.63 2197.32,16.21 2195.74,20.04 2195.74,76.34 2183.23,88.85 2145.52,88.85 2133.01,76.34 2133.01,20.04 2131.42,16.21 2127.6,14.63 2014.14,14.63 2010.32,16.21 2008.73,20.04 2008.73,76.34 1996.22,88.85 1958.51,88.85 1946,76.34 1946,20.04 1944.42,16.21 1940.59,14.63 1256.26,14.63 1252.43,16.21 1250.85,20.04 1250.85,76.34 1238.34,88.85 1200.63,88.85 1188.12,76.34 1188.12,20.04 1186.54,16.21 1182.71,14.63 1069.25,14.63 1065.43,16.21 1063.84,20.04 1063.84,76.34 1051.33,88.85 1013.62,88.85 1001.11,76.34 1001.11,20.04 999.53,16.21 995.7,14.63 563,14.63 559.17,16.21 557.59,20.04 557.59,549.61 20.04,549.61 16.21,551.19 14.63,555.02

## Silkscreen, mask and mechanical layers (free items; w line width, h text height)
Top Overlay:
  drawing of 5591 lines, arcs and shapes, not listed
  text "3V3_STLINK" at 2528,3781 h35
  text "STLINK" at 1680,3750 h35
  text "GND" at 3175.3,3598.1 h35 r90
  text "GND" at 2596,3562 h35 r90
  text "JTCK" at 2687,3535 h35 r90
  text "JTMS" at 2481,3532 h35 r90
  text "GND" at 241.1,3512.7 h35
  text "E5V" at 2507,3419 h35
  text "LineIN" at 455,3353 h35 r90
  text "LineOUT" at 1004,3345 h35 r90
  text "GND" at 2512,3307 h35
  text "20" at 2925,3195 h35
  text "10" at 2735,3190 h35
  text "PH5" at 2945,3135 h35
  text "PC11" at 3058,3131 h35
  text "PC2" at 2945,3065 h35
  text "PA15" at 3061,3064 h35
  text "www.st.com/stm32f7-discovery" at 20,3000 h50
  text "PC3" at 2945,2985 h35
  text "PH14" at 3060,2985 h35
  text "PH4" at 2945,2910 h35
  text "PH13" at 3060,2910 h35
  text "GND" at 3065,2835 h35
  text "5V" at 2950,2830 h35
  text "QSPI" at 1117.64,2806.5 h35
  text "VDD" at 2085,2770 h35
  text "5V" at 3095,2755 h35
  text "GND" at 2946,2754 h35
  text "PI1" at 2945,2680 h35
  text "PB0" at 3060,2680 h35
  text "PF6" at 2945,2595 h35
  text "PA4" at 3060,2595 h35
  text "3V3" at 2085,2525 h35
  text "PF7" at 2945,2520 h35
  text "PF11" at 3060,2515 h35
  text "VCP_TX" at 1855,2493 h35 r90
  text "VCP_RX" at 1917,2492 h35 r90
  text "Audio" at 450,2465 h35
  text "Codec" at 610,2465 h35
  text "PI0" at 2945,2450 h35
  text "PB11" at 3060,2445 h35
  text "SPKR" at 57.1,2420.7 h35
  text "1" at 2750,2390 h35
  text "11" at 2890,2385 h35
  text "TAG" at 2361.1,2383.7 h35
  text "Table for P1" at 2770,2320 h35
  text "B" at 1095,2205 h35
  text "A" at 995,2110 h35
  text "SPKL" at 57.1,2075.7 h35
  text "STLINK" at 2779,2008 h35
  text "3V3" at 2089,1963 h35
  text "NRST" at 2199,1963 h35
  text "USB_HS" at 2779,1963 h35
  text "1V8" at 26,1955 h35
  text "D15" at 2565,1950 h35
  text "E5V" at 2779,1913 h35
  text "TMS" at 2089,1908 h35
  text "TRST" at 2194,1908 h35
  text "800mA" at 27,1906 h35
  text "MAX" at 32,1859 h35
  text "GND" at 2094,1858 h35
  text "TDI" at 2194,1858 h35
  text "USB_FS" at 2779,1858 h35
  text "D14" at 2565,1850 h35
  text "TCK" at 2094,1808 h35
  text "USB_STLINK" at 2779,1803 h35
  text "GND" at 2094,1758 h35
  text "TDO" at 2194,1758 h35
  text "AVDD" at 2565,1750 h35
  text "GND" at 2565,1670 h35
  text "STM32F723IEK" at 1222,1575 h35
  text "D13" at 2565,1560 h35
  text "E5V" at 30,1526 h35
  text "3V3" at 460,1485 h35
  text "800mA" at 29,1468 h35
  text "D12" at 2565,1460 h35
  text "MAX" at 33,1420 h35
  text "NRST" at 430,1385 h35
  text "D11" at 2565,1350 h35
  text "3V3" at 460,1290 h35
  text "D10" at 2565,1235 h35
  text "A" at 1275,1195 h35
  text "B" at 695,1190 h35
  text "5V" at 460,1185 h35
  text "D9" at 2570,1150 h35
  text "GND" at 460,1095 h35
  text "D8" at 2570,1050 h35
  text "S" at 2323,992 h35 r90
  text "D" at 2404,992 h35 r90
  text "GND" at 460,990 h35
  text "Table for P2" at 2755,975 h35
  text "PSRAM" at 1465,925 h35
  text "6" at 2680,920 h35
  text "12" at 2790,920 h35
  text "D7" at 2570,880 h35
  text "VIN" at 465,874 h35
  text "3V3" at 3006,847 h35
  text "3V3" at 2869,845 h35
  text "<11.5V" at 567,797 h35
  text "VIN" at 477,792 h35
  text "STM32F723E-DISCO" at 1478.78,790.59 h70
  text "D6" at 2570,785 h35
  text "GND" at 2869,755 h35
  text "GND" at 3011,752 h35
  text "MB1260D" at 2180,715 h40
  text "A0" at 490,675 h35
  text "D5" at 2570,670 h35
  text "PH2" at 3006,652 h35
  text "PI1" at 2869,650 h35
  text "A1" at 490,580 h35
  text "D4" at 2570,580 h35
  text "PG12" at 3006,552 h35
  text "PI2" at 2869,550 h35
  text "A2" at 490,485 h35
  text "D3" at 2570,480 h35
  text "PF11" at 3006,452 h35
  text "PI3" at 2869,450 h35
  text "D2" at 2570,385 h35
  text "A3" at 490,380 h35
  text "PB11" at 3006,352 h35
  text "PI0" at 2869,350 h35
  text "1" at 2690,295 h35
  text "7" at 2795,295 h35
  text "D1" at 2570,285 h35
  text "A4" at 490,280 h35
  text "PMOD" at 2722.1,240.7 h35
  text "D0" at 2570,200 h35
  text "A5" at 490,180 h35
  text "USB HS" at 1065,90 h35
  text "USB FS" at 1985,90 h35
  text "GND" at 2797.1,30.7 h35
  text "SILKSCREEN, (PRIMARY)" at 1943.2,-2056.3 h60
  text "SILKSCREEN, (PRIMARY)" at 1943.2,-2056.3 h60
Bottom Overlay:
  drawing of 5533 lines, arcs and shapes, not listed
  text "3V3_STLINK" at 2860,3765 h35
  text "STLINK" at 2160,3720 h35
  text "GND" at 407,3701 h35
  text "GND" at 2550,3570 h35 r270
  text "JTMS" at 2460,3560 h35 r270
  text "JTCK" at 2660,3550 h35 r270
  text "GND" at 3040,3486 h35
  text "STM32F723E-DISCO" at 2105.72,3450.1 h70
  text "E5V" at 2815,3405 h35
  text "www.st.com/stm32f7-discovery" at 2147,3372 h50
  text "GND" at 2815,3320 h35
  text "1" at 2490,3060 h35 r270
  text "1" at 2555,3060 h35 r270
  text "UART" at 2610,3030 h35 r270
  text "RTS,PF8" at 2255,2975 h35 r270
  text "RX,PF6" at 2315,2975 h35 r270
  text "TX,PF7" at 2375,2975 h35 r270
  text "CTS,PF9" at 2435,2975 h35 r270
  text "0" at 2490,2825 h35 r270
  text "1" at 2560,2825 h35 r270
  text "VDD" at 2220,2760 h35
  text "RX,PF6" at 2315,2745 h35 r270
  text "SCK,PI1" at 2260,2740 h35 r270
  text "TX,PF7" at 2370,2740 h35 r270
  text "NSS,PI0" at 2435,2735 h35 r270
  text "UART/SPI" at 2610,2710 h35 r270
  text "VCPTX" at 1775,2660 h35
  text "VCPRX" at 2045,2660 h35
  text "0" at 2490,2550 h35 r270
  text "0" at 2555,2550 h35 r270
  text "3V3" at 2225,2525 h35
  text "SPI" at 2610,2520 h35 r270
  text "MOSI,PI3" at 2380,2435 h35 r270
  text "NSS,PI0" at 2435,2435 h35 r270
  text "MB1260D" at 245,2430 h50 r270
  text "SCK,PI1" at 2260,2430 h35 r270
  text "MISO,PI2" at 2320,2430 h35 r270
  text "SPKR" at 170,2405 h35
  text "PMOD#4" at 2260,2180 h35 r270
  text "PMOD#3" at 2320,2180 h35 r270
  text "PMOD#2" at 2375,2180 h35 r270
  text "PMOD#1" at 2435,2180 h35 r270
  text "SPKL" at 170,2097 h35
  text "SEL_1,PI10" at 2495,2090 h35 r270
  text "SEL_0,PH15" at 2555,2090 h35 r270
  text "PH4" at 2645,1950 h35
  text "USER&WAKEUP" at 3146,1949 h35
  text "PH5" at 2645,1850 h35
  text "VREF+" at 2710,1750 h35
  text "GND" at 2645,1645 h35
  text "PA5" at 2645,1550 h35
  text "B" at 2324,1509 h35 r90
  text "D" at 2405,1509 h35 r90
  text "3V3" at 570,1485 h35
  text "PB4" at 2645,1450 h35
  text "LCD" at 1505,1435 h75
  text "NRST" at 570,1385 h35
  text "PB5" at 2645,1345 h35
  text "3V3" at 565,1290 h35
  text "PA1" at 2645,1245 h35
  text "5V" at 565,1185 h35
  text "PH6" at 2645,1145 h35
  text "GND" at 565,1095 h35
  text "RESET" at 3050,1080 h35
  text "PE4" at 2645,1050 h35
  text "WIFI" at 35,990 h35 r270
  text "GND" at 565,990 h35
  text "PE3" at 2645,890 h35
  text "<11.5V" at 760,830 h35
  text "VIN" at 855,825 h35
  text "PE6" at 2645,790 h35
  text "PA6" at 550,685 h35
  text "PB0" at 2645,685 h35
  text "<-" at 455,595 h35
  text "PA4" at 550,590 h35
  text "PH3" at 2645,590 h35
  text "<-" at 455,485 h35
  text "PC4" at 550,485 h35
  text "PE5" at 2645,485 h35
  text "PC5" at 2645,385 h35
  text "PF10" at 550,365 h35
  text "PA2" at 2645,280 h35
  text "PC0" at 550,275 h35
  text "PC1" at 550,190 h35
  text "PA3" at 2645,180 h35
  text "GND" at 2895,30 h35
  text "USB HS" at 1525,15 h35
  text "USB FS" at 2490,15 h35
  text "SILKSCREEN, (SECONDARY)" at 3028.8,-2048.37 h60
  text "SILKSCREEN, (SECONDARY)" at 3028.8,-2048.37 h60
Top Paste:
  region: 940.37,776.5 861.63,776.5 861.63,765.67 826.2,765.67 826.2,749.92 861.63,749.92 861.63,740.08 826.2,740.08 826.2,724.33 861.63,724.33 861.63,713.5 940.37,713.5 940.37,724.33 975.8,724.33 975.8,740.08 940.37,740.08 940.37,749.92 975.8,749.92 975.8,765.67 940.37,765.67 940.37,776.5
  region: 1088.41,292.88 1072.66,292.88 1072.66,300.75 1080.53,300.75 1080.53,316.5 1088.41,316.5 1088.41,292.88
  region: 1139.59,292.88 1155.34,292.88 1155.34,300.75 1147.47,300.75 1147.47,316.5 1139.59,316.5 1139.59,292.88
  region: 1088.41,277.12 1072.66,277.12 1072.66,269.25 1080.53,269.25 1080.53,253.5 1088.41,253.5 1088.41,277.12
  region: 1139.59,277.12 1155.34,277.12 1155.34,269.25 1147.47,269.25 1147.47,253.5 1139.59,253.5 1139.59,277.12
  text "SOLDER PASTE (PRIMARY)" at 1943.2,-2056.3 h60
  text "SOLDER PASTE (PRIMARY)" at 1943.2,-2056.3 h60
Bottom Paste:
  text "SOLDER PASTE (SECONDARY)" at 1943.2,-2056.3 h60
  text "SOLDER PASTE (SECONDARY)" at 1943.2,-2056.3 h60
Top Solder:
  region: 940.37,776.5 861.63,776.5 861.63,765.67 826.2,765.67 826.2,749.92 861.63,749.92 861.63,740.08 826.2,740.08 826.2,724.33 861.63,724.33 861.63,713.5 940.37,713.5 940.37,724.33 975.8,724.33 975.8,740.08 940.37,740.08 940.37,749.92 975.8,749.92 975.8,765.67 940.37,765.67 940.37,776.5
  region: 1090.41,318.5 1090.41,290.88 1070.66,290.88 1070.66,302.75 1078.53,302.75 1078.53,318.5 1090.41,318.5
  region: 1137.59,318.5 1149.47,318.5 1149.47,302.75 1157.34,302.75 1157.34,290.88 1137.59,290.88 1137.59,318.5
  region: 1090.41,251.5 1078.53,251.5 1078.53,267.25 1070.66,267.25 1070.66,279.12 1090.41,279.12 1090.41,251.5
  region: 1137.59,251.5 1137.59,279.12 1157.34,279.12 1157.34,267.25 1149.47,267.25 1149.47,251.5 1137.59,251.5
  text "SOLDER MASK (PRIMARY)" at 1943.2,-2056.3 h60
  text "SOLDER MASK (PRIMARY)" at 1943.2,-2056.3 h60
Bottom Solder:
  text "SOLDER MASK (SECONDARY)" at 1943.2,-2056.3 h60
  text "SOLDER MASK (SECONDARY)" at 1943.2,-2056.3 h60
Mechanical 1:
  lines w1: 134,2840 134,2875 170,2875 170,2840 134,2840 ; 135.69,870.11 235.09,870.11 235.09,932.43 135.69,932.43 135.69,870.11 ; 140.69,2375.11 240.09,2375.11 240.09,2437.43 140.69,2437.43 140.69,2375.11 ; 145,3350 145,3460 181,3460 181,3350 145,3350 ; 150.69,1770.11 250.09,1770.11 250.09,1832.43 150.69,1832.43 150.69,1770.11 ; 245,2770 245,2880 281,2880 281,2770 245,2770 ; 245,3350 245,3460 281,3460 281,3350 245,3350 ; 518.78,2246.26 689.01,2246.26 689.01,2437.92 518.78,2437.92 518.78,2246.26 ; 715,2840 715,2875 751,2875 751,2840 715,2840 ; 725,3350 725,3460 761,3460 761,3350 725,3350 ; 830,2770 830,2880 866,2880 866,2770 830,2770 ; 835,3350 835,3460 871,3460 871,3350 835,3350 ; 849.21,3107.97 849.21,3177.33 885.21,3177.33 885.21,3107.97 849.21,3107.97 ; 964.21,3107.97 964.21,3177.33 1000.21,3177.33 1000.21,3107.97 964.21,3107.97 ; 1200,1631.82 1200,2033.18 1206.82,2040 1360,2040 1390,2070 1505,2070 1535,2040 1615,2040 1615,1970 1640,1945 1640,1670 1615,1645 1615,1605 1615,1600 1594.13,1579.13 1545.87,1579.13 1520,1605 1226.82,1605 1200,1631.82 ; 1675,1140 1675,1344.28 1770,1344.28 1785,1359.28 1785,1390 1790,1395 1830,1395 1835,1390 1835,1349.28 1840,1344.28 1950,1344.28 1950,1140 1942,1132 1912,1132 1904,1140 1675,1140
DIMENSION:
  drawing of 513 lines, arcs and shapes, not listed
  text "FAB DARWING & DRILL LEGEND" at 1943.2,-2056.3 h60
  text "FAB DARWING & DRILL LEGEND" at 1943.2,-2056.3 h60
LAY2:
  lines w8: 2276,1118 2276,1128 2276,1178 2336,1178 2336,1118 2276,1118 ; 2357,1118 2357,1128 2357,1178 2417,1178 2417,1118 2357,1118
  text "2" at 2324,1136 h35 r90
  text "D" at 2405,1136 h35 r90
  text "2" at 2443.2,-1906.3 h75
  text "2" at 2443.2,-1906.3 h75
  text "LAYER 2 (GND PLANE)" at 1943.2,-2056.3 h60
  text "LAYER 2 (GND PLANE)" at 1943.2,-2056.3 h60
LAY4:
  lines w8: 2276,1258 2276,1268 2276,1318 2336,1318 2336,1258 2276,1258 ; 2357,1258 2357,1268 2357,1318 2417,1318 2417,1258 2357,1258
  text "4" at 2325,1300 h35 r90
  text "D" at 2405,1274 h35 r90
  text "4" at 2443.2,-1906.3 h75
  text "4" at 2443.2,-1906.3 h75
  text "LAYER 4 (INTERNAL SIGNAL)" at 1943.2,-2056.3 h60
  text "LAYER 4 (INTERNAL SIGNAL)" at 1943.2,-2056.3 h60
LAY5:
  lines w8: 2276,1328 2276,1338 2276,1388 2336,1388 2336,1328 2276,1328 ; 2357,1328 2357,1338 2357,1388 2417,1388 2417,1328 2357,1328
  text "5" at 2323,1368 h35 r90
  text "D" at 2404,1368 h35 r90
  text "5" at 2443.2,-1906.3 h75
  text "5" at 2443.2,-1906.3 h75
  text "LAYER 5 (GND PLANE)" at 1943.2,-2056.3 h60
  text "LAYER 5 (GND PLANE)" at 1943.2,-2056.3 h60
LAY3:
  lines w8: 2276,1188 2276,1198 2276,1248 2336,1248 2336,1188 2276,1188 ; 2357,1188 2357,1198 2357,1248 2417,1248 2417,1188 2357,1188
  text "3" at 2325,1202 h35 r90
  text "D" at 2406,1202 h35 r90
  text "3" at 2443.2,-1906.3 h75
  text "3" at 2443.2,-1906.3 h75
  text "LAYER 3 (VCC PLANE)" at 1943.2,-2056.3 h60
  text "LAYER 3 (VCC PLANE)" at 1943.2,-2056.3 h60
LCD_REF_160412:
  drawing of 122 lines, arcs and shapes, not listed
  text "LCD" at 1438.19,1805.12 h75
FAB_NOTES:
  drawing of 205 lines, arcs and shapes, not listed
DRAWING_ORIGIN:
  lines w1: -25,0 25,0 ; 0,-25 0,25
Drill Drawing:
  drawing of 25393 lines, arcs and shapes, not listed
  text "6" at -1462,10961 h130
  text "5" at 2038,10961 h130
  text "4" at 5538,10961 h130
  text "3" at 9038,10961 h130
  text "2" at 12538,10961 h130
  text "1" at 16038,10961 h130
  text "REVISIONS" at 15140,10710 h85
  text "REVISIONS" at 15140,10710 h85
  text "REV" at 13690,10460 h75
  text "REV" at 13690,10460 h75
  text "DESCRIPTION" at 14240,10460 h75
  text "DESCRIPTION" at 14240,10460 h75
  text "DATE" at 16390,10460 h75
  text "DATE" at 16390,10460 h75
  text "APPROVED" at 17090,10460 h75
  text "APPROVED" at 17090,10460 h75
  text "1.0" at 13690,10260 h75
  text "1.0" at 13690,10260 h75
  text "EDITION ORIGINALE" at 14240,10260 h75
  text "EDITION ORIGINALE" at 14240,10260 h75
  text "2008-**-**" at 16240,10260 h75
  text "2008-**-**" at 16240,10260 h75
  text "***" at 17250,10260 h75
  text "***" at 17250,10260 h75
  text "D" at -3462,8661 h130
  text "D" at 17838,8661 h130
  text "4" at 12139.2,7215.4 h75
  text "4" at 12139.2,7215.4 h75
  text "LAYER STUCK-UP" at 12339.2,7215.4 h75
  text "SOLDERMASK & SILKSCREEN" at 14099.2,6975.4 h60
  text "TOP     (0.5 oz cu+planted)" at 14099.2,6855.4 h60
  text "PREPREG  3.9 mil" at 12779.2,6690.4 h60
  text "LAYER 2 (1 oz)" at 14099.2,6555.4 h60
  text "CORE     4  mil" at 12779.2,6455.4 h60
  text "LAYER 3 (1 oz)" at 14099.2,6355.4 h60
  text "63 mil" at 11907.2,6282.9 h75
  text "PREPREG  ** mil" at 12779.2,6190.4 h60
  text "+/-10%" at 11949.2,6175.4 h50
  text "5" at 4592,6164.6 h100
  text "IMPEDANCE TABLE" at 4825.8,6122.8 h100
  text "IMPEDANCE TABLE" at 4825.8,6122.8 h100
  text "LAYER 4 (1 oz)" at 14099.2,6055.4 h60
  text "CORE     4  mil" at 12779.2,5955.4 h60
  text "LAYER 5 (1 oz)" at 14099.2,5855.4 h60
  text "LAYER" at 4750.8,5828.8 h75
  text "LAYER" at 4750.8,5828.8 h75
  text "TOLERANCE" at 8500.8,5828.8 h75
  text "TOLERANCE" at 8500.8,5828.8 h75
  text "TRACE" at 5500.8,5818.8 h75
  text "TRACE" at 5500.8,5818.8 h75
  text "SPACEING" at 6050.8,5818.8 h75
  text "SPACEING" at 6050.8,5818.8 h75
  text "IMPEDANCE" at 6800.8,5818.8 h75
  text "IMPEDANCE" at 6800.8,5818.8 h75
  text "IMPEDANCE" at 7700.8,5818.8 h75
  text "IMPEDANCE" at 7700.8,5818.8 h75
  text "(mil)" at 5550.8,5728.8 h50
  text "(mil)" at 5550.8,5728.8 h50
  text "(Single end)" at 6850.8,5728.8 h50
  text "(Single end)" at 6850.8,5728.8 h50
  text "(mil)" at 6150.8,5718.8 h50
  text "(mil)" at 6150.8,5718.8 h50
  text "(Differential)" at 7700.8,5718.8 h50
  text "(Differential)" at 7700.8,5718.8 h50
  text "PREPREG  3.9 mil" at 12779.2,5690.4 h60
  text "1,6" at 4745.8,5582.8 h75
  text "1,6" at 4745.8,5582.8 h75
  text "5.0" at 5545.8,5572.8 h75
  text "5.0" at 5545.8,5572.8 h75
  text "BOTTOM  (0.5 oz cu+planted)" at 14099.2,5555.4 h60
  text "N/A" at 6200.8,5518.8 h75
  text "N/A" at 6200.8,5518.8 h75
  text "55 OHM" at 6850.8,5508.8 h75
  text "55 OHM" at 6850.8,5508.8 h75
  text "N/A" at 7850.8,5508.8 h75
  text "N/A" at 7850.8,5508.8 h75
  text "+/-10%" at 8600.8,5508.8 h75
  text "+/-10%" at 8600.8,5508.8 h75
  text "4.0" at 5535.8,5452.8 h75
  text "4.0" at 5535.8,5452.8 h75
  text "4" at 4745.8,5442.8 h75
  text "4" at 4745.8,5442.8 h75
  text "SOLDERMASK & SILKSCREEN" at 14099.2,5435.4 h60
  text "N/A" at 6955.8,5272.8 h75
  text "100 OHM" at 7765.8,5262.8 h75
  text "+/-10%" at 8600.8,5258.8 h75
  text "+/-10%" at 8600.8,5258.8 h75
  text "6 LAYER STACKING" at 12719.2,5255.4 h75
  text "90 OHM" at 7759.8,5016.8 h75
  text "1,6" at 4745.8,5015.65 h75
  text "6.1" at 5535.8,5015.65 h75
  text "+/-10%" at 8606.8,5014.8 h75
  text "8.9" at 6175.8,5005.65 h75
  text "N/A" at 6960.8,4993.8 h75
  text "C" at -3462,4761 h130
  text "C" at 17838,4761 h130
  text "PCB SPECIFICATIONS:" at 10970,3435.4 h85
  text "Symbol" at 4685.84,3434.01 h118.11
  text "Hit Count" at 5148.39,3434.01 h118.11
  text "Finished Hole Size" at 5701.87,3434.01 h118.11
  text "Plated" at 6692.33,3434.01 h118.11
  text "Hole Length" at 7098.54,3434.01 h118.11
  text "Hole Type" at 7775.1,3434.01 h118.11
  text "Tolerance" at 8366.22,3434.01 h118.11
  text "A. MATERIAL;" at 10970,3235.4 h85
  text "FR-4," at 12720,3235.4 h85
  text "TG-170" at 13670,3235.4 h85
  text "TG-150" at 14420,3235.4 h85
  text "TG-140" at 15270,3235.4 h85
  text "2" at 5343.1,3230.13 h98.43
  text "24,00mil" at 5973.96,3230.13 h98.43
  text "PTH" at 6753.16,3230.13 h98.43
  text "51,00mil" at 7214.23,3230.13 h98.43
  text "Slot" at 7936.04,3230.13 h98.43
  text "+5.0/-5.0" at 8427.38,3230.13 h98.43
  text "B. MATERIAL FAMILY;" at 10970,3035.4 h85
  text "N/A." at 12720,3035.4 h85
  text "4" at 5342.11,3026.26 h98.43
  text "30,00mil" at 5974.51,3026.26 h98.43
  text "PTH" at 6753.16,3026.26 h98.43
  text "33,00mil" at 7214.23,3026.26 h98.43
  text "Slot" at 7936.04,3026.26 h98.43
  text "+5.0/-5.0" at 8427.38,3026.26 h98.43
  text "C. SOLDERMASK COLOR;" at 10970,2835.4 h85
  text "GREEN" at 12870,2835.4 h85
  text "BLUE" at 13620,2835.4 h85
  text "RED" at 14470,2835.4 h85
  text "BLACK" at 15320,2835.4 h85
  text "4" at 5342.11,2822.38 h98.43
  text "33,00mil" at 5974.51,2822.38 h98.43
  text "PTH" at 6753.16,2822.38 h98.43
  text "59,00mil" at 7214.23,2822.38 h98.43
  text "Slot" at 7936.04,2822.38 h98.43
  text "+5.0/-5.0" at 8427.38,2822.38 h98.43
  text "D. SILKSCREEN COLOR;" at 10970,2635.4 h85
  text "WHITE" at 12870,2635.4 h85
  text "YELLOW" at 13620,2635.4 h85
  text "BLACK" at 14470,2635.4 h85
  text "35" at 5318.61,2618.51 h98.43
  text "6,00mil" at 5998.79,2618.51 h98.43
  text "PTH" at 6753.16,2618.51 h98.43
  text "-" at 7363.74,2618.51 h98.43
  text "Round" at 7886.42,2618.51 h98.43
  text "+3.0/-3.0" at 8427.38,2618.51 h98.43
  text "E. SURFACE FINISH;" at 10970,2435.4 h85
  text "ENIG" at 12870,2435.4 h85
  text "IMMERSION SILVER" at 13620,2435.4 h85
  text "IMMERSION TIN" at 15320,2435.4 h85
  text "196" at 5297.31,2414.63 h98.43
  text "8,00mil" at 5998.93,2414.63 h98.43
  text "PTH" at 6753.16,2414.63 h98.43
  text "-" at 7363.74,2414.63 h98.43
  text "Round" at 7886.42,2414.63 h98.43
  text "+3.0/-3.0" at 8427.38,2414.63 h98.43
  text "HASL" at 12870,2235.4 h85
  text "HASL(PB-FREE)" at 13620,2235.4 h85
  text "GOLDEN FINGER" at 15320,2235.4 h85
  text "231" at 5299.9,2210.76 h98.43
  text "10,00mil" at 5977.45,2210.76 h98.43
  text "PTH" at 6753.16,2210.76 h98.43
  text "-" at 7363.74,2210.76 h98.43
  text "Round" at 7886.42,2210.76 h98.43
  text "+3.0/-3.0" at 8427.38,2210.76 h98.43
  text "NO" at 12870,2035.4 h85
  text "YES" at 13620,2035.4 h85
  text "(SEE IMPEDANCE TABLE FOR DETAIL INFORMATION)" at 13820,2035.4 h85
  text "F. IMPEDANCE CONTROL;" at 11068.5,2027.5 h85
  text "389" at 5294.3,2006.88 h98.43
  text "12,00mil" at 5977.45,2006.88 h98.43
  text "PTH" at 6753.16,2006.88 h98.43
  text "-" at 7363.74,2006.88 h98.43
  text "Round" at 7886.42,2006.88 h98.43
  text "+3.0/-3.0" at 8427.38,2006.88 h98.43
  text "G. THROUGH VIA;" at 10970,1835.4 h85
  text "PLUG THE VIAS WHICH ARE COVERED WITH SOLDERMASK ONE OR TWO SIDE." at 12420,1835.4 h85
  text "2" at 5343.1,1803.01 h98.43
  text "33,00mil" at 5974.51,1803.01 h98.43
  text "PTH" at 6753.16,1803.01 h98.43
  text "-" at 7363.74,1803.01 h98.43
  text "Round" at 7886.42,1803.01 h98.43
  text "+3.0/-3.0" at 8427.38,1803.01 h98.43
  text "PLUG MATERIAL:" at 12420,1635.4 h85
  text "SOLDERMASK" at 14020,1635.4 h85
  text "NON-CONDUCTIVE EPOXY." at 15320,1635.4 h85
  text "32" at 5319.16,1599.13 h98.43
  text "36,00mil" at 5974.51,1599.13 h98.43
  text "PTH" at 6753.16,1599.13 h98.43
  text "-" at 7363.74,1599.13 h98.43
  text "Round" at 7886.42,1599.13 h98.43
  text "+3.0/-3.0" at 8427.38,1599.13 h98.43
  text "SEE LAYER STACK-UP SEQUENCE FOR OVERALL THICKNESS." at 12422,1428 h85
  text "H. STACK-UP;" at 11056.7,1423.6 h85
  text "54" at 5318.96,1395.26 h98.43
  text "40,00mil" at 5973.18,1395.26 h98.43
  text "PTH" at 6753.16,1395.26 h98.43
  text "-" at 7363.74,1395.26 h98.43
  text "Round" at 7886.42,1395.26 h98.43
  text "+3.0/-3.0" at 8427.38,1395.26 h98.43
  text "3" at 5343.34,1191.38 h98.43
  text "138,00mil" at 5952.96,1191.38 h98.43
  text "PTH" at 6753.16,1191.38 h98.43
  text "-" at 7363.74,1191.38 h98.43
  text "Round" at 7886.42,1191.38 h98.43
  text "+3.0/-3.0" at 8427.38,1191.38 h98.43
  text "PCB REQUIREMENTS:" at 10960,1135.4 h85
  text "B" at 17838,1061 h130
  text "B" at -3462,1048 h130
  text "4" at 5342.11,987.5 h98.43
  text "79,00mil" at 5974.75,987.5 h98.43
  text "NPTH" at 6721.34,987.5 h98.43
  text "-" at 7363.74,987.5 h98.43
  text "Round" at 7886.42,987.5 h98.43
  text "+2.0/-2.0" at 8427.38,987.5 h98.43
  text "1. THIS BOARD WILL CONFORM TO:" at 10910,935.4 h85
  text "IPC-A-600. CURRENT REV., CLASS II" at 10910,785.4 h85
  text "1" at 5352.35,783.63 h98.43
  text "138,00mil" at 5952.96,783.63 h98.43
  text "NPTH" at 6721.34,783.63 h98.43
  text "-" at 7363.74,783.63 h98.43
  text "Round" at 7886.42,783.63 h98.43
  text "+2.0/-2.0" at 8427.38,783.63 h98.43
  text "IPC-6012, CURRENT REV., CLASS II" at 10910,635.4 h85
  text "3" at 5343.34,579.75 h98.43
  text "39,00mil" at 5974.51,579.75 h98.43
  text "PTH" at 6753.16,579.75 h98.43
  text "-" at 7363.74,579.75 h98.43
  text "Round" at 7886.42,579.75 h98.43
  text "2. UNLESS OTHERWISE SPECIFIED ALL HOLE DIMENSIONS APPLY AFTER PLATING." at 10910,425.4 h85
  text "960 Total" at 5185.4,375.88 h98.43
  text "ALL HOLES SHALL BE LOCATED WITHIN .003\" DIAMETER OF TRUE POSITION." at 10910,275.4 h85
  text "Slot definitions :" at 4685.84,233.17 h98.43
  text "Routed Path Length" at 5356.72,233.17 h98.43
  text "= Calculated from tool start centre position to tool end centre position." at 6188.17,233.17 h98.43
  text "Hole Length" at 5356.72,151.62 h98.43
  text "= Routed Path Length + Tool Size = Slot length as defined in the PCB layout" at 5879.52,151.62 h98.43
  text "3. PLATED HOLE WALL THICKNESS SHALL NOT BE LESS THAN .001 INCH MINIMUM" at 10910,75.4 h85
  text "AVERAGE, WITH NO READING LESS THAN .0008 BY COROSS SECTION." at 11090,-64.6 h85
  text "4. MATERIAL FR4 RATING 94V-0 MINIMUM EPOXY GLASS LAMINATE." at 10910,-274.6 h85
  text "5. BOARD SHALL BE LPI SOLDER MASKED OVER BARE COPPER BOTH SIDES PER" at 10910,-454.6 h85
  text "IPC-SM-840 CLASS II." at 10910,-604.6 h85
  text "6. SILKSCREEN SHALL BE PERMANENT NON-CONDUCTIVE INK AND WITH NO OVERLAP" at 10910,-804.6 h85
  text "ON ANY COMPONENT PAD OR THROUGH HOLE." at 10910,-954.6 h85
  text "7. MFGR, TO LEGIBLY ETCH OR STAMP/SCREEN WITH PERMANENT NON-CONDUCTIVE INK" at 10910,-1154.6 h85
  text "D. MFGR. LOGO" at 12760,-1284.6 h85
  text "A. U.L. CODE" at 11200,-1304.6 h85
  text "E. SUCCESSFUL ELECTRICAL BOARD TEST." at 12760,-1424.6 h85
  text "B. DATE CODE" at 11200,-1444.6 h85
  text "C. FLAMMABILITY RATING" at 11200,-1584.6 h85
  text "8. REMOVE THE FLASHS WHICH SMALLER THAN HOLE SIZE." at 10910,-1794.6 h85
  text "COMPANY NAME:" at 3493.2,-1856.3 h60
  text "LAYER:" at 1893.2,-1906.3 h75
  text "9. REMOVE ALL SHAPE EDGES AND BURRS .005 MAXIMUM." at 10910,-1994.6 h85
  text "ST" at 3643.2,-2006.3 h75
  text "PROJECT NAME:" at 3493.2,-2156.3 h60
  text "DESIGNED BY SOFER" at 623.2,-2176.3 h60
  text "10. PLEASE USE THE SUPPLIED IPC 356 NETLIST TO VERIFY BOARD BEFORE" at 10910,-2204.6 h85
  text "www.sofer.com.cn" at 643.2,-2276.3 h60
  text "DESIGNER:" at 1943.2,-2306.3 h60
  text "Shelley" at 2443.2,-2306.3 h60
  text "MB1260" at 3643.2,-2306.3 h75
  text "FABRICATING BOARD." at 10910,-2354.6 h85
  text "Tel : +86 21 - 6482 6908" at 443.2,-2456.3 h60
  text "PROJECT NUMBER:" at 3493.2,-2456.3 h60
  text "REV" at 4693.2,-2456.3 h60
  text "Mail: design@sofer.com.cn" at 443.2,-2556.3 h60
  text "DATE:" at 1943.2,-2556.3 h60
  text "2016.12.29" at 2243.2,-2556.3 h60
  text "D031-022A4" at 3643.2,-2606.3 h75
  text "D" at 4793.2,-2606.3 h75
  text "A" at -3462,-3139 h130
  text "A" at 17838,-3139 h130
  text "UNLESS OTHERWISE SPECIFIED" at 10590,-3440 h75
  text "SIGNATURES" at 12490,-3490 h75
  text "DATE" at 13890,-3490 h75
  text "LOGO" at 14590,-3640 h130
  text "COMPANY NAME" at 16090,-3640 h130
  text "DRAWN" at 12490,-3690 h75
  text "YY-MM-DD" at 13790,-3690 h75
  text "DIMENSIONS ARE IN INCHES" at 10640,-3740 h75
  text "TOLERANCES ON;" at 10640,-3890 h75
  text "CHECKED" at 12490,-3890 h75
  text "YY-MM-DD" at 13790,-3890 h75
  text "2 PL DECIMALS +" at 10640,-4040 h75
  text "TITLE" at 14490,-4040 h100
  text "ENGRG" at 12490,-4090 h75
  text "YY-MM-DD" at 13790,-4090 h75
  text "PROJECT NAME *" at 15240,-4140 h130
  text "3 PL DECIMALS +" at 10640,-4190 h75
  text "ISSUED" at 12490,-4290 h75
  text "ANGLES +" at 10640,-4340 h75
  text "SIZE" at 14515,-4415 h75
  text "B" at 14915,-4415 h75
  text "DWG NO" at 15265,-4415 h75
  text "*********" at 15865,-4415 h75
  text "REV" at 17165,-4415 h75
  text "**" at 17465,-4415 h75
  text "FRACTIONS +" at 10640,-4490 h75
  text "SCALE" at 14515,-4665 h75
  text "1:1" at 14915,-4665 h75
  text "SHEET" at 16515,-4665 h75
  text "1 OF 1" at 17115,-4665 h75
  text "2" at 12533,-4938 h130
  text "6" at -1462,-4939 h130
  text "5" at 2038,-4939 h130
  text "1" at 16038,-4939 h130
  text "3" at 9024,-4942 h130
  text "4" at 5530,-4945 h130
LAY10:
  text "10" at 2393.2,-1906.3 h75
  text "10" at 2393.2,-1906.3 h75
  text "LAYER 10(INTERNAL SIGNAL)" at 1943.2,-2056.3 h60
  text "LAYER 10(INTERNAL SIGNAL)" at 1943.2,-2056.3 h60
LAY7:
  text "7" at 2443.2,-1906.3 h75
  text "7" at 2443.2,-1906.3 h75
  text "LAYER 7 (INTERNAL SIGNAL)" at 1943.2,-2056.3 h60
  text "LAYER 7 (INTERNAL SIGNAL)" at 1943.2,-2056.3 h60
